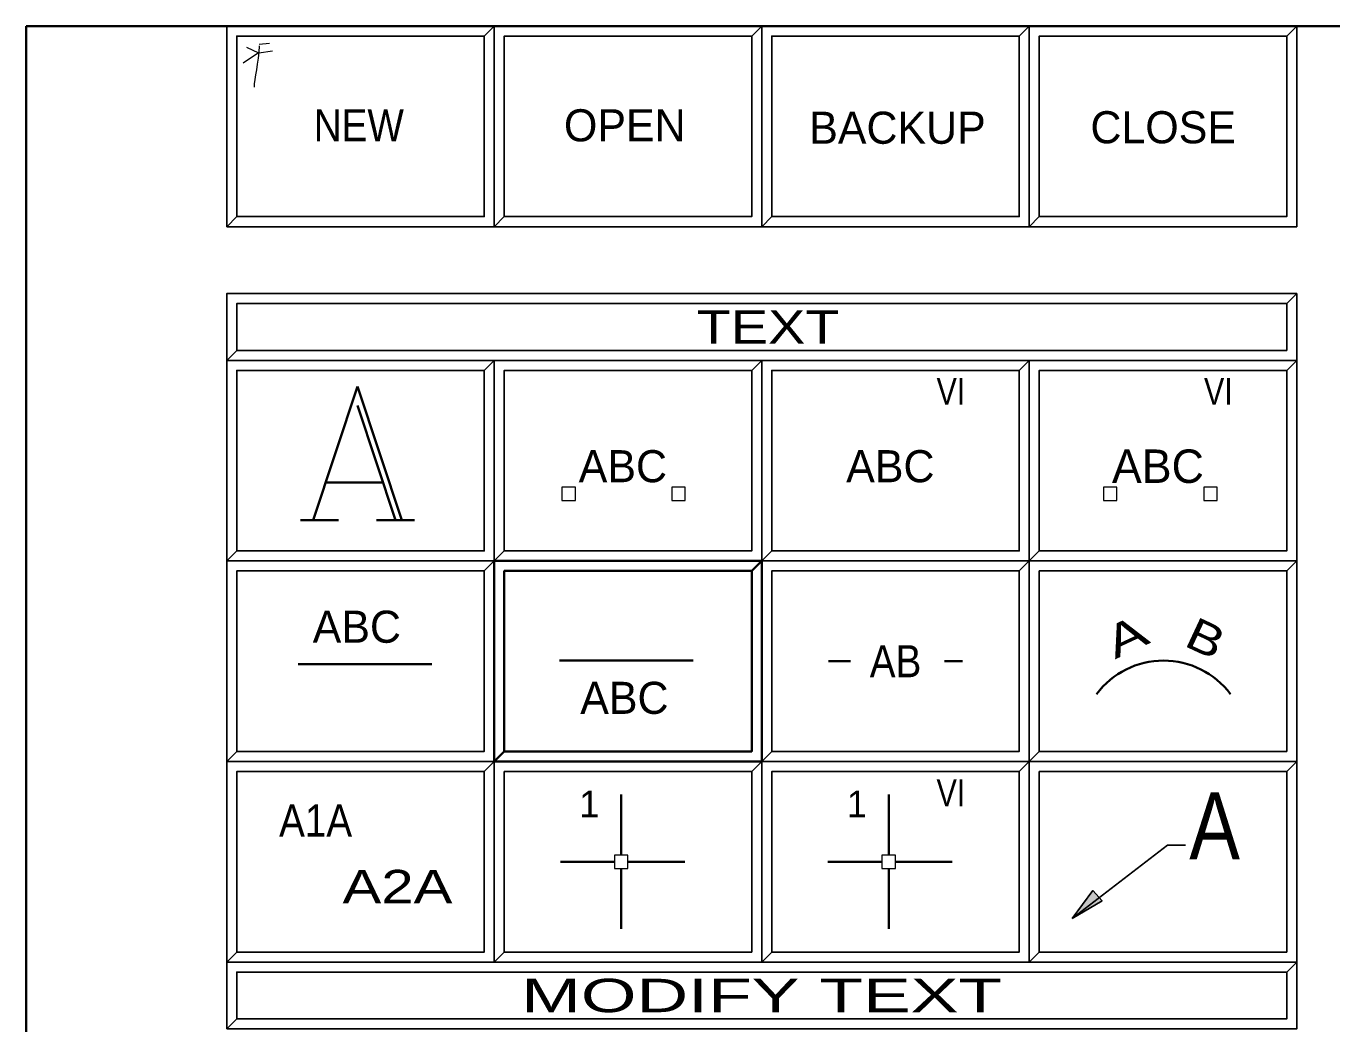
# Model space of a CAD drawing. Extents: x 95906.8 to 95923.6, y 90964.8 to 90972.8.
# Drawn here: x 95906.832 to 95908.785, y 90971.269 to 90972.762 of the extents above; entities that cross this region are included whole.
import ezdxf
from ezdxf.enums import TextEntityAlignment as Align

# ---------------------------------------------------------------- set-up
doc = ezdxf.new("R2010")
doc.units = 0
doc.header["$LTSCALE"] = 0.019
for name, color, linetype, lineweight in [('1', 7, 'Continuous', 25), ('11', 7, 'Continuous', 25), ('12', 7, 'Continuous', 25), ('17', 7, 'Continuous', 25), ('18', 7, 'Continuous', 25), ('2', 7, 'Continuous', 13), ('3', 7, 'Continuous', 25), ('6', 7, 'Continuous', 35), ('7', 7, 'Continuous', 35)]:
    doc.layers.add(name, color=color, linetype=linetype, lineweight=lineweight)

msp = doc.modelspace()

# ---------------------------------------------------------------- hatches: boundary and pattern name
at = {"layer": '6'}
msp.add_hatch(color=256, dxfattribs=at).paths.add_polyline_path([(95908.3963, 90971.4268), (95908.4276, 90971.4686), (95908.4412, 90971.4534)])

# ---------------------------------------------------------------- linework, layer by layer
at = {"layer": '1'}
for points in [[(95907.1323, 90972.4617), (95907.5323, 90972.4617), (95907.5323, 90972.7617), (95907.1323, 90972.7617)], [(95907.5323, 90972.4617), (95907.9323, 90972.4617), (95907.9323, 90972.7617), (95907.5323, 90972.7617)], [(95907.9323, 90972.4617), (95908.3323, 90972.4617), (95908.3323, 90972.7617), (95907.9323, 90972.7617)], [(95908.3323, 90972.4617), (95908.7323, 90972.4617), (95908.7323, 90972.7617), (95908.3323, 90972.7617)], [(95907.1323, 90972.2617), (95908.7323, 90972.2617), (95908.7323, 90972.3617), (95907.1323, 90972.3617)], [(95907.1323, 90971.9617), (95907.5323, 90971.9617), (95907.5323, 90972.2617), (95907.1323, 90972.2617)], [(95907.5323, 90971.9617), (95907.9323, 90971.9617), (95907.9323, 90972.2617), (95907.5323, 90972.2617)], [(95907.9323, 90971.9617), (95908.3323, 90971.9617), (95908.3323, 90972.2617), (95907.9323, 90972.2617)], [(95908.3323, 90971.9617), (95908.7323, 90971.9617), (95908.7323, 90972.2617), (95908.3323, 90972.2617)], [(95907.1323, 90971.6617), (95907.5323, 90971.6617), (95907.5323, 90971.9617), (95907.1323, 90971.9617)], [(95907.9323, 90971.6617), (95908.3323, 90971.6617), (95908.3323, 90971.9617), (95907.9323, 90971.9617)], [(95908.3323, 90971.6617), (95908.7323, 90971.6617), (95908.7323, 90971.9617), (95908.3323, 90971.9617)], [(95907.1323, 90971.3617), (95907.5323, 90971.3617), (95907.5323, 90971.6617), (95907.1323, 90971.6617)], [(95907.5323, 90971.3617), (95907.9323, 90971.3617), (95907.9323, 90971.6617), (95907.5323, 90971.6617)], [(95907.9323, 90971.3617), (95908.3323, 90971.3617), (95908.3323, 90971.6617), (95907.9323, 90971.6617)], [(95908.3323, 90971.3617), (95908.7323, 90971.3617), (95908.7323, 90971.6617), (95908.3323, 90971.6617)], [(95907.1323, 90971.2617), (95908.7323, 90971.2617), (95908.7323, 90971.3617), (95907.1323, 90971.3617)]]:
    msp.add_lwpolyline(points, close=True, dxfattribs=at)
at = {"layer": '1', "lineweight": 35}
msp.add_lwpolyline([(95907.5323, 90971.6617), (95907.9323, 90971.6617), (95907.9323, 90971.9617), (95907.5323, 90971.9617)], close=True, dxfattribs=at)
at = {"layer": '11', "lineweight": 13}
for p, q in [((95907.1803, 90972.7217), (95907.2008, 90972.7247)), ((95907.181, 90972.7348), (95907.196, 90972.7364))]:
    msp.add_line(p, q, dxfattribs=at)
at = {"layer": '11'}
for points in [[(95907.1473, 90972.4767), (95907.5173, 90972.4767), (95907.5173, 90972.7467), (95907.1473, 90972.7467)], [(95907.5473, 90972.4767), (95907.9173, 90972.4767), (95907.9173, 90972.7467), (95907.5473, 90972.7467)], [(95907.9473, 90972.4767), (95908.3173, 90972.4767), (95908.3173, 90972.7467), (95907.9473, 90972.7467)], [(95908.3473, 90972.4767), (95908.7173, 90972.4767), (95908.7173, 90972.7467), (95908.3473, 90972.7467)], [(95907.5473, 90971.9767), (95907.9173, 90971.9767), (95907.9173, 90972.2467), (95907.5473, 90972.2467)], [(95907.9473, 90971.9767), (95908.3173, 90971.9767), (95908.3173, 90972.2467), (95907.9473, 90972.2467)], [(95908.3473, 90971.9767), (95908.7173, 90971.9767), (95908.7173, 90972.2467), (95908.3473, 90972.2467)], [(95907.1473, 90971.6767), (95907.5173, 90971.6767), (95907.5173, 90971.9467), (95907.1473, 90971.9467)], [(95907.9473, 90971.6767), (95908.3173, 90971.6767), (95908.3173, 90971.9467), (95907.9473, 90971.9467)], [(95908.3473, 90971.6767), (95908.7173, 90971.6767), (95908.7173, 90971.9467), (95908.3473, 90971.9467)], [(95907.1473, 90971.3767), (95907.5173, 90971.3767), (95907.5173, 90971.6467), (95907.1473, 90971.6467)], [(95907.5473, 90971.3767), (95907.9173, 90971.3767), (95907.9173, 90971.6467), (95907.5473, 90971.6467)], [(95907.9473, 90971.3767), (95908.3173, 90971.3767), (95908.3173, 90971.6467), (95907.9473, 90971.6467)], [(95908.3473, 90971.3767), (95908.7173, 90971.3767), (95908.7173, 90971.6467), (95908.3473, 90971.6467)]]:
    msp.add_lwpolyline(points, close=True, dxfattribs=at)
at = {"layer": '11', "lineweight": 13}
msp.add_lwpolyline([(95907.1616, 90972.7304), (95907.1799, 90972.7215), (95907.157, 90972.7061)], dxfattribs=at)
at = {"layer": '11', "lineweight": 35}
msp.add_lwpolyline([(95907.5473, 90971.6767), (95907.9173, 90971.6767), (95907.9173, 90971.9467), (95907.5473, 90971.9467)], close=True, dxfattribs=at)
at = {"layer": '11', "lineweight": 13}
msp.add_open_spline([(95907.181, 90972.732), (95907.1798, 90972.707), (95907.1729, 90972.6828), (95907.1734, 90972.6702)], degree=3, dxfattribs=at)
at = {"layer": '12'}
msp.add_lwpolyline([(95907.1473, 90971.9767), (95907.5173, 90971.9767), (95907.5173, 90972.2467), (95907.1473, 90972.2467)], close=True, dxfattribs=at)
at = {"layer": '17'}
msp.add_lwpolyline([(95907.1473, 90972.2767), (95908.7173, 90972.2767), (95908.7173, 90972.3467), (95907.1473, 90972.3467)], close=True, dxfattribs=at)
at = {"layer": '18'}
msp.add_lwpolyline([(95907.1473, 90971.2767), (95908.7173, 90971.2767), (95908.7173, 90971.3467), (95907.1473, 90971.3467)], close=True, dxfattribs=at)
at = {"layer": '2'}
for points in [[(95907.1323, 90972.7617), (95907.1323, 90972.4617), (95907.1473, 90972.4767), (95907.1473, 90972.7467), (95907.5173, 90972.7467), (95907.5323, 90972.7617)], [(95907.5323, 90972.7617), (95907.5323, 90972.4617), (95907.5473, 90972.4767), (95907.5473, 90972.7467), (95907.9173, 90972.7467), (95907.9323, 90972.7617)], [(95907.9323, 90972.7617), (95907.9323, 90972.4617), (95907.9473, 90972.4767), (95907.9473, 90972.7467), (95908.3173, 90972.7467), (95908.3323, 90972.7617)], [(95908.3323, 90972.7617), (95908.3323, 90972.4617), (95908.3473, 90972.4767), (95908.3473, 90972.7467), (95908.7173, 90972.7467), (95908.7323, 90972.7617)], [(95907.1323, 90972.3617), (95907.1323, 90972.2617), (95907.1473, 90972.2767), (95907.1473, 90972.3467), (95908.7173, 90972.3467), (95908.7323, 90972.3617)], [(95907.1323, 90972.2617), (95907.1323, 90971.9617), (95907.1473, 90971.9767), (95907.1473, 90972.2467), (95907.5173, 90972.2467), (95907.5323, 90972.2617)], [(95907.5323, 90972.2617), (95907.5323, 90971.9617), (95907.5473, 90971.9767), (95907.5473, 90972.2467), (95907.9173, 90972.2467), (95907.9323, 90972.2617)], [(95907.9323, 90972.2617), (95907.9323, 90971.9617), (95907.9473, 90971.9767), (95907.9473, 90972.2467), (95908.3173, 90972.2467), (95908.3323, 90972.2617)], [(95908.3323, 90972.2617), (95908.3323, 90971.9617), (95908.3473, 90971.9767), (95908.3473, 90972.2467), (95908.7173, 90972.2467), (95908.7323, 90972.2617)], [(95907.1323, 90971.9617), (95907.1323, 90971.6617), (95907.1473, 90971.6767), (95907.1473, 90971.9467), (95907.5173, 90971.9467), (95907.5323, 90971.9617)], [(95907.9323, 90971.9617), (95907.9323, 90971.6617), (95907.9473, 90971.6767), (95907.9473, 90971.9467), (95908.3173, 90971.9467), (95908.3323, 90971.9617)], [(95908.3323, 90971.9617), (95908.3323, 90971.6617), (95908.3473, 90971.6767), (95908.3473, 90971.9467), (95908.7173, 90971.9467), (95908.7323, 90971.9617)], [(95907.1323, 90971.6617), (95907.1323, 90971.3617), (95907.1473, 90971.3767), (95907.1473, 90971.6467), (95907.5173, 90971.6467), (95907.5323, 90971.6617)], [(95907.5323, 90971.6617), (95907.5323, 90971.3617), (95907.5473, 90971.3767), (95907.5473, 90971.6467), (95907.9173, 90971.6467), (95907.9323, 90971.6617)], [(95907.9323, 90971.6617), (95907.9323, 90971.3617), (95907.9473, 90971.3767), (95907.9473, 90971.6467), (95908.3173, 90971.6467), (95908.3323, 90971.6617)], [(95908.3323, 90971.6617), (95908.3323, 90971.3617), (95908.3473, 90971.3767), (95908.3473, 90971.6467), (95908.7173, 90971.6467), (95908.7323, 90971.6617)], [(95907.1323, 90971.3617), (95907.1323, 90971.2617), (95907.1473, 90971.2767), (95907.1473, 90971.3467), (95908.7173, 90971.3467), (95908.7323, 90971.3617)]]:
    msp.add_lwpolyline(points, close=True, dxfattribs=at)
at = {"layer": '2', "lineweight": 35}
msp.add_lwpolyline([(95907.5323, 90971.9617), (95907.5323, 90971.6617), (95907.5473, 90971.6767), (95907.5473, 90971.9467), (95907.9173, 90971.9467), (95907.9323, 90971.9617)], close=True, dxfattribs=at)
at = {"layer": '3'}
for points in [[(95907.1323, 90972.4617), (95907.5323, 90972.4617), (95907.5323, 90972.7617), (95907.5173, 90972.7467), (95907.5173, 90972.4767), (95907.1473, 90972.4767)], [(95907.5323, 90972.4617), (95907.9323, 90972.4617), (95907.9323, 90972.7617), (95907.9173, 90972.7467), (95907.9173, 90972.4767), (95907.5473, 90972.4767)], [(95907.9323, 90972.4617), (95908.3323, 90972.4617), (95908.3323, 90972.7617), (95908.3173, 90972.7467), (95908.3173, 90972.4767), (95907.9473, 90972.4767)], [(95908.3323, 90972.4617), (95908.7323, 90972.4617), (95908.7323, 90972.7617), (95908.7173, 90972.7467), (95908.7173, 90972.4767), (95908.3473, 90972.4767)], [(95907.1323, 90972.2617), (95908.7323, 90972.2617), (95908.7323, 90972.3617), (95908.7173, 90972.3467), (95908.7173, 90972.2767), (95907.1473, 90972.2767)], [(95907.1323, 90971.9617), (95907.5323, 90971.9617), (95907.5323, 90972.2617), (95907.5173, 90972.2467), (95907.5173, 90971.9767), (95907.1473, 90971.9767)], [(95907.5323, 90971.9617), (95907.9323, 90971.9617), (95907.9323, 90972.2617), (95907.9173, 90972.2467), (95907.9173, 90971.9767), (95907.5473, 90971.9767)], [(95907.9323, 90971.9617), (95908.3323, 90971.9617), (95908.3323, 90972.2617), (95908.3173, 90972.2467), (95908.3173, 90971.9767), (95907.9473, 90971.9767)], [(95908.3323, 90971.9617), (95908.7323, 90971.9617), (95908.7323, 90972.2617), (95908.7173, 90972.2467), (95908.7173, 90971.9767), (95908.3473, 90971.9767)], [(95907.1323, 90971.6617), (95907.5323, 90971.6617), (95907.5323, 90971.9617), (95907.5173, 90971.9467), (95907.5173, 90971.6767), (95907.1473, 90971.6767)], [(95907.9323, 90971.6617), (95908.3323, 90971.6617), (95908.3323, 90971.9617), (95908.3173, 90971.9467), (95908.3173, 90971.6767), (95907.9473, 90971.6767)], [(95908.3323, 90971.6617), (95908.7323, 90971.6617), (95908.7323, 90971.9617), (95908.7173, 90971.9467), (95908.7173, 90971.6767), (95908.3473, 90971.6767)], [(95907.1323, 90971.3617), (95907.5323, 90971.3617), (95907.5323, 90971.6617), (95907.5173, 90971.6467), (95907.5173, 90971.3767), (95907.1473, 90971.3767)], [(95907.5323, 90971.3617), (95907.9323, 90971.3617), (95907.9323, 90971.6617), (95907.9173, 90971.6467), (95907.9173, 90971.3767), (95907.5473, 90971.3767)], [(95907.9323, 90971.3617), (95908.3323, 90971.3617), (95908.3323, 90971.6617), (95908.3173, 90971.6467), (95908.3173, 90971.3767), (95907.9473, 90971.3767)], [(95908.3323, 90971.3617), (95908.7323, 90971.3617), (95908.7323, 90971.6617), (95908.7173, 90971.6467), (95908.7173, 90971.3767), (95908.3473, 90971.3767)], [(95907.1323, 90971.2617), (95908.7323, 90971.2617), (95908.7323, 90971.3617), (95908.7173, 90971.3467), (95908.7173, 90971.2767), (95907.1473, 90971.2767)]]:
    msp.add_lwpolyline(points, close=True, dxfattribs=at)
at = {"layer": '3', "lineweight": 35}
msp.add_lwpolyline([(95907.5323, 90971.6617), (95907.9323, 90971.6617), (95907.9323, 90971.9617), (95907.9173, 90971.9467), (95907.9173, 90971.6767), (95907.5473, 90971.6767)], close=True, dxfattribs=at)
at = {"layer": '6'}
for p, q in [((95907.3278, 90972.2225), (95907.2617, 90972.0225)), ((95907.3278, 90972.2225), (95907.394, 90972.0225)), ((95907.3278, 90972.1942), (95907.3845, 90972.0225)), ((95907.2806, 90972.0792), (95907.3656, 90972.0792)), ((95907.2428, 90972.0225), (95907.2995, 90972.0225)), ((95907.3562, 90972.0225), (95907.4129, 90972.0225)), ((95907.239, 90971.8071), (95907.439, 90971.8071)), ((95907.6297, 90971.8127), (95907.8297, 90971.8127)), ((95908.0323, 90971.8117), (95908.0648, 90971.8117)), ((95908.2323, 90971.8117), (95908.2054, 90971.8117)), ((95907.7221, 90971.5218), (95907.7221, 90971.6124)), ((95908.1221, 90971.5218), (95908.1221, 90971.6124)), ((95907.7121, 90971.5118), (95907.6313, 90971.5118)), ((95907.7321, 90971.5118), (95907.8171, 90971.5118)), ((95908.1121, 90971.5118), (95908.0313, 90971.5118)), ((95908.1321, 90971.5118), (95908.2171, 90971.5118)), ((95907.7221, 90971.4112), (95907.7221, 90971.5018)), ((95908.1221, 90971.4112), (95908.1221, 90971.5018))]:
    msp.add_line(p, q, dxfattribs=at)
at = {"layer": '6', "lineweight": 13}
for points in [[(95907.6336, 90972.0522), (95907.6536, 90972.0522), (95907.6536, 90972.0722), (95907.6336, 90972.0722)], [(95907.7979, 90972.0522), (95907.8179, 90972.0522), (95907.8179, 90972.0722), (95907.7979, 90972.0722)], [(95908.4434, 90972.0522), (95908.4634, 90972.0522), (95908.4634, 90972.0722), (95908.4434, 90972.0722)], [(95908.5935, 90972.0522), (95908.6135, 90972.0522), (95908.6135, 90972.0722), (95908.5935, 90972.0722)], [(95907.7121, 90971.5018), (95907.7321, 90971.5018), (95907.7321, 90971.5218), (95907.7121, 90971.5218)], [(95908.1121, 90971.5018), (95908.1321, 90971.5018), (95908.1321, 90971.5218), (95908.1121, 90971.5218)]]:
    msp.add_lwpolyline(points, close=True, dxfattribs=at)
at = {"layer": '6', "lineweight": 25}
msp.add_lwpolyline([(95908.5659, 90971.5364), (95908.539, 90971.5364), (95908.3963, 90971.4268)], dxfattribs=at)
msp.add_lwpolyline([(95908.3963, 90971.4268), (95908.4276, 90971.4686), (95908.4412, 90971.4534)], close=True, dxfattribs=at)
at = {"layer": '6'}
msp.add_arc((95908.5331, 90971.6876), 0.125, 36.8699, 143.1301, dxfattribs=at)
at = {"layer": '7'}
msp.add_lwpolyline([(95906.8323, 90972.7617), (95918.8323, 90972.7617), (95918.8323, 90964.7617), (95906.8323, 90964.7617)], close=True, dxfattribs=at)

# ---------------------------------------------------------------- texts
at = {"layer": '6'}
for s, height, width, p in [('NEW', 0.048, 0.9, (95907.3298, 90972.5893)), ('VI', 0.04, 0.85, (95908.2152, 90972.1953)), ('VI', 0.04, 0.85, (95908.6151, 90972.1953)), ('AB', 0.048, 0.9, (95908.1324, 90971.7877)), ('VI', 0.04, 0.85, (95908.2152, 90971.5948)), ('A', 0.1, 0.85, (95908.6095, 90971.5154)), ('A1A', 0.048, 0.9, (95907.2652, 90971.5494)), (' A2A', 0.05, 1.3, (95907.3755, 90971.4496))]:
    msp.add_text(s, height=height, dxfattribs=dict(at, width=width)).set_placement(p, align=Align.CENTER)
for s, height, p in [('OPEN', 0.048, (95907.7275, 90972.5893)), ('BACKUP', 0.048, (95908.1353, 90972.5857)), ('CLOSE', 0.048, (95908.5326, 90972.5864)), ('ABC', 0.048, (95907.7246, 90972.0794)), ('ABC', 0.048, (95908.1246, 90972.0794)), ('ABC', 0.04999, (95908.5247, 90972.0784)), ('ABC', 0.048, (95907.3268, 90971.8393)), ('ABC', 0.048, (95907.7269, 90971.7329)), ('1', 0.04, (95907.6745, 90971.5781)), ('1', 0.04, (95908.0745, 90971.5781))]:
    msp.add_text(s, height=height, dxfattribs=at).set_placement(p, align=Align.CENTER)
for s, rotation, width, p in [('A', 25, 1.4, (95908.4877, 90971.827)), ('B', 335, 1.25, (95908.5861, 90971.8243))]:
    msp.add_text(s, height=0.048, rotation=rotation, dxfattribs=dict(at, width=width)).set_placement(p, align=Align.CENTER)
at = {"layer": '7'}
for s, height, width, p in [('TEXT', 0.05, 1.25, (95907.9417, 90972.2867)), ('      MODIFY TEXT      ', 0.04999, 1.6, (95907.9322, 90971.2867))]:
    msp.add_text(s, height=height, dxfattribs=dict(at, width=width)).set_placement(p, align=Align.CENTER)

doc.saveas('drawing.dxf')
